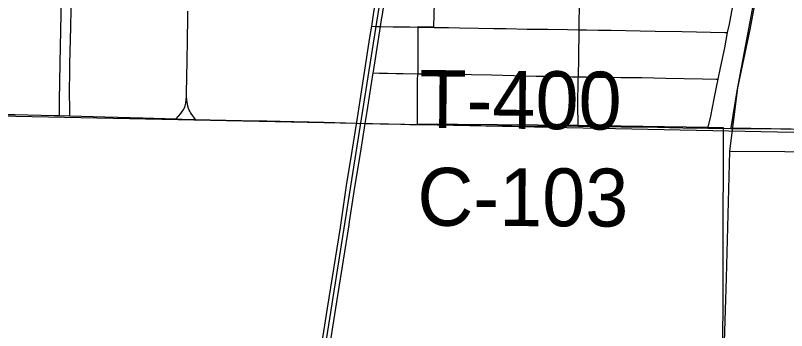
# Model space of a CAD drawing. Extents: x 0 to 34, y 0 to 22.
# Drawn here: x 2.454 to 3.211, y 14.756 to 15.065 of the extents above; entities that cross this region are included whole.
import ezdxf

# ---------------------------------------------------------------- set-up
doc = ezdxf.new("R2010")
doc.units = 0
for name, color, linetype in [('GM_X_City_Street', 7, 'Continuous'), ('GM_X_Corporation', 7, 'Continuous'), ('GM_X_County_Road', 7, 'Continuous'), ('GM_X_County_Road_Text', 7, 'Continuous'), ('GM_X_Minor_River', 7, 'Continuous'), ('GM_X_Rail_Line', 7, 'Continuous'), ('GM_X_State_Route', 7, 'Continuous'), ('GM_X_Township_Road', 7, 'Continuous'), ('GM_X_Township_Road_Text', 7, 'Continuous')]:
    doc.layers.add(name, color=color, linetype=linetype)

msp = doc.modelspace()

# ---------------------------------------------------------------- linework, layer by layer
at = {"layer": 'GM_X_City_Street'}
for points in [[(2.49768, 14.96704), (2.49775, 14.97442), (2.49781, 14.98129), (2.49853, 15.01852), (2.49941, 15.06631), (2.49948, 15.07124), (2.49976, 15.09114), (2.49993, 15.11337), (2.50014, 15.11643), (2.50081, 15.11934), (2.50283, 15.12451)], [(2.50775, 14.96677), (2.50775, 14.97401), (2.50774, 14.97953), (2.50765, 14.98334), (2.50796, 15.01754), (2.5087, 15.05362), (2.50931, 15.07131), (2.50939, 15.07352), (2.50981, 15.08591), (2.50961, 15.09269), (2.50912, 15.09882), (2.50851, 15.1044), (2.50748, 15.11011), (2.50626, 15.1148), (2.50483, 15.11969), (2.50283, 15.12451)], [(2.62241, 14.98522), (2.62241, 14.98933), (2.623, 15.02035), (2.6234, 15.04143), (2.62367, 15.0625), (2.62376, 15.06926)], [(2.61232, 14.96372), (2.61658, 14.96897), (2.61811, 14.97085), (2.61913, 14.97226), (2.62029, 14.97444), (2.62096, 14.97657), (2.62151, 14.97907), (2.62241, 14.98522)], [(2.63126, 14.96312), (2.62693, 14.96903), (2.62625, 14.96994), (2.62542, 14.97138), (2.62492, 14.97244), (2.62437, 14.97384), (2.62364, 14.97627), (2.62321, 14.97834), (2.62291, 14.98017), (2.6226, 14.98278), (2.62241, 14.98522)]]:
    msp.add_lwpolyline(points, dxfattribs=at)
at = {"layer": 'GM_X_Corporation'}
for points in [[(2.41416, 15.97585), (3.42156, 15.95047), (3.40873, 14.94631), (2.39105, 14.96729)], [(2.36635, 14.1), (3.39599, 14.1), (3.40873, 14.94631), (2.39105, 14.96729)]]:
    msp.add_lwpolyline(points, close=True, dxfattribs=at)
for points in [[(3.19089, 15.14435), (3.16209, 14.99135), (3.15616, 14.955), (3.33366, 14.95213)], [(3.14781, 14.4499), (3.14898, 14.95508), (3.13362, 14.95525), (3.00613, 14.95729), (2.84885, 14.95871), (2.84882, 15.00344), (2.84958, 15.00862), (2.84957, 15.02774), (2.84967, 15.05433), (2.86497, 15.05401), (2.86558, 15.0779)]]:
    msp.add_lwpolyline(points, dxfattribs=at)
at = {"layer": 'GM_X_County_Road'}
for points in [[(2.37546, 14.96859), (2.39031, 14.96832), (2.43997, 14.96811), (2.45391, 14.96788), (2.49262, 14.96717), (2.49768, 14.96704)], [(2.49768, 14.96704), (2.50775, 14.96677), (2.54216, 14.96586), (2.5793, 14.96477), (2.61232, 14.96372)], [(2.61232, 14.96372), (2.61804, 14.96354), (2.63126, 14.96312)], [(2.63126, 14.96312), (2.64548, 14.96267), (2.67642, 14.96205), (2.70121, 14.96167), (2.7275, 14.96111), (2.75691, 14.96037), (2.78911, 14.95944)], [(2.78911, 14.95944), (2.79767, 14.9592), (2.79971, 14.95916), (2.81235, 14.9589), (2.83253, 14.95849), (2.84117, 14.95831), (2.84908, 14.95815)], [(2.84908, 14.95815), (2.86349, 14.95817), (2.88138, 14.95778), (2.91111, 14.95735), (2.94173, 14.9569), (2.96353, 14.95658), (2.99338, 14.95677), (3.00636, 14.95673)], [(3.00636, 14.95673), (3.00957, 14.95673), (3.04877, 14.95602), (3.06743, 14.95578), (3.08423, 14.95549), (3.09605, 14.95532), (3.10911, 14.95503), (3.13385, 14.9547)], [(3.13385, 14.9547), (3.14021, 14.95462), (3.15639, 14.95445), (3.1774, 14.95419), (3.20535, 14.95384), (3.2363, 14.95346), (3.27858, 14.95282), (3.31276, 14.9523), (3.33419, 14.95202)]]:
    msp.add_lwpolyline(points, dxfattribs=at)
at = {"layer": 'GM_X_Minor_River'}
for points in [[(3.21302, 15.25097), (3.19848, 15.18182), (3.18753, 15.1198), (3.1749, 15.05137), (3.16293, 14.99432), (3.155, 14.93223), (3.1516, 14.80775), (3.14918, 14.72387)], [(3.155, 14.93223), (3.37195, 14.93074), (3.47353, 14.93076)]]:
    msp.add_lwpolyline(points, dxfattribs=at)
at = {"layer": 'GM_X_Rail_Line'}
msp.add_lwpolyline([(2.65698, 14.1), (2.90883, 15.68759), (2.96003, 16.05223), (2.64019, 16.66968)], dxfattribs=at)
at = {"layer": 'GM_X_State_Route'}
for points in [[(2.78927, 14.96044), (2.79673, 15.00714), (2.80215, 15.04342), (2.80394, 15.05456), (2.80579, 15.06612), (2.81129, 15.10087), (2.81624, 15.13213), (2.8193, 15.15142), (2.8232, 15.17603), (2.83384, 15.24533), (2.83471, 15.25101), (2.84029, 15.28663), (2.84637, 15.32532), (2.84866, 15.34017), (2.8489, 15.34169), (2.8492, 15.34363), (2.85105, 15.35416), (2.86018, 15.41252), (2.86567, 15.44818), (2.86765, 15.46106), (2.8717, 15.48874), (2.87545, 15.51329), (2.87568, 15.51694), (2.87587, 15.52938)], [(2.81398, 15.06325), (2.81414, 15.06424), (2.81974, 15.1006)], [(2.79767, 14.9592), (2.79952, 14.9709), (2.80547, 15.00875), (2.8057, 15.0102), (2.8126, 15.05436), (2.81398, 15.06325)], [(2.70999, 14.4594), (2.71601, 14.49719), (2.72339, 14.54396), (2.72802, 14.57293), (2.73608, 14.62489), (2.74468, 14.67796), (2.75029, 14.71323), (2.75592, 14.74894), (2.76071, 14.77797), (2.77328, 14.85724), (2.77939, 14.89847), (2.78488, 14.93223), (2.78898, 14.95864), (2.78911, 14.95944), (2.78927, 14.96044)], [(2.78218, 14.86269), (2.78751, 14.89665), (2.79301, 14.92976), (2.79767, 14.9592)], [(2.71903, 14.46118), (2.7207, 14.47222), (2.72584, 14.50604), (2.73136, 14.54042), (2.73748, 14.57974), (2.74539, 14.62947), (2.75732, 14.70564), (2.77082, 14.79037), (2.78173, 14.85978), (2.78218, 14.86269)]]:
    msp.add_lwpolyline(points, dxfattribs=at)
at = {"layer": 'GM_X_Township_Road'}
for points in [[(3.00741, 15.05124), (3.00751, 15.05998), (3.00766, 15.07164), (3.0079, 15.08351), (3.00805, 15.09092), (3.00817, 15.09688)], [(3.15315, 15.04833), (3.15479, 15.05668), (3.15805, 15.07272), (3.16014, 15.08301), (3.16232, 15.0937)], [(2.80394, 15.05456), (2.80794, 15.05447), (2.8126, 15.05436)], [(2.8126, 15.05436), (2.82506, 15.05409), (2.83156, 15.05401), (2.84135, 15.05389), (2.8499, 15.05378)], [(2.8499, 15.05378), (2.85459, 15.05368), (2.85912, 15.05358), (2.8652, 15.05346)], [(2.8652, 15.05346), (2.87931, 15.05339), (2.89013, 15.05315), (2.90855, 15.05282), (2.92377, 15.05254), (2.93586, 15.05231), (2.95643, 15.05186), (2.97674, 15.05162), (2.99608, 15.05138), (3.00741, 15.05124)], [(3.00668, 15.00501), (3.00707, 15.02403), (3.00741, 15.05124)], [(3.00741, 15.05124), (3.01475, 15.05111), (3.02655, 15.0509), (3.03893, 15.05067), (3.06743, 15.05016), (3.08212, 15.0499), (3.10847, 15.04942), (3.15035, 15.0484), (3.15315, 15.04833)], [(3.14373, 15.00279), (3.14609, 15.01395), (3.15021, 15.03339), (3.15315, 15.04833)], [(2.80547, 15.00875), (2.81152, 15.00865), (2.81943, 15.00853), (2.82798, 15.00839), (2.83485, 15.00828), (2.84981, 15.00806)], [(2.84981, 15.00806), (2.86588, 15.00794), (2.87707, 15.00789), (2.88708, 15.00767), (2.90201, 15.00736), (2.92137, 15.00681), (2.96529, 15.00556), (2.97774, 15.00551), (2.99266, 15.00526), (3.00074, 15.00514), (3.00668, 15.00501)], [(3.00636, 14.95673), (3.00634, 14.9588), (3.00622, 14.97618), (3.00664, 15.0029), (3.00668, 15.00501)], [(3.00668, 15.00501), (3.01004, 15.00495), (3.01434, 15.00483), (3.02053, 15.00475), (3.02798, 15.00466), (3.03853, 15.00454), (3.04848, 15.00448), (3.05717, 15.00441), (3.06883, 15.00417), (3.09263, 15.00368), (3.11053, 15.00332), (3.12855, 15.00295), (3.14174, 15.00276), (3.14373, 15.00279)], [(3.13385, 14.9547), (3.13403, 14.95547), (3.13652, 14.96649), (3.13825, 14.97501), (3.13987, 14.98355), (3.14171, 14.99331), (3.14373, 15.00279)]]:
    msp.add_lwpolyline(points, dxfattribs=at)

# ---------------------------------------------------------------- texts
at = {"layer": 'GM_X_County_Road_Text'}
msp.add_text('C-103', height=0.056818, rotation=359.72928, dxfattribs=at).set_placement((2.84866, 14.85902))
at = {"layer": 'GM_X_Township_Road_Text'}
msp.add_text('T-400', height=0.056818, rotation=359.44012, dxfattribs=at).set_placement((2.8504, 14.95496))

doc.saveas('drawing.dxf')
